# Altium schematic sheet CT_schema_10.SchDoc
size 297 x 239 mm
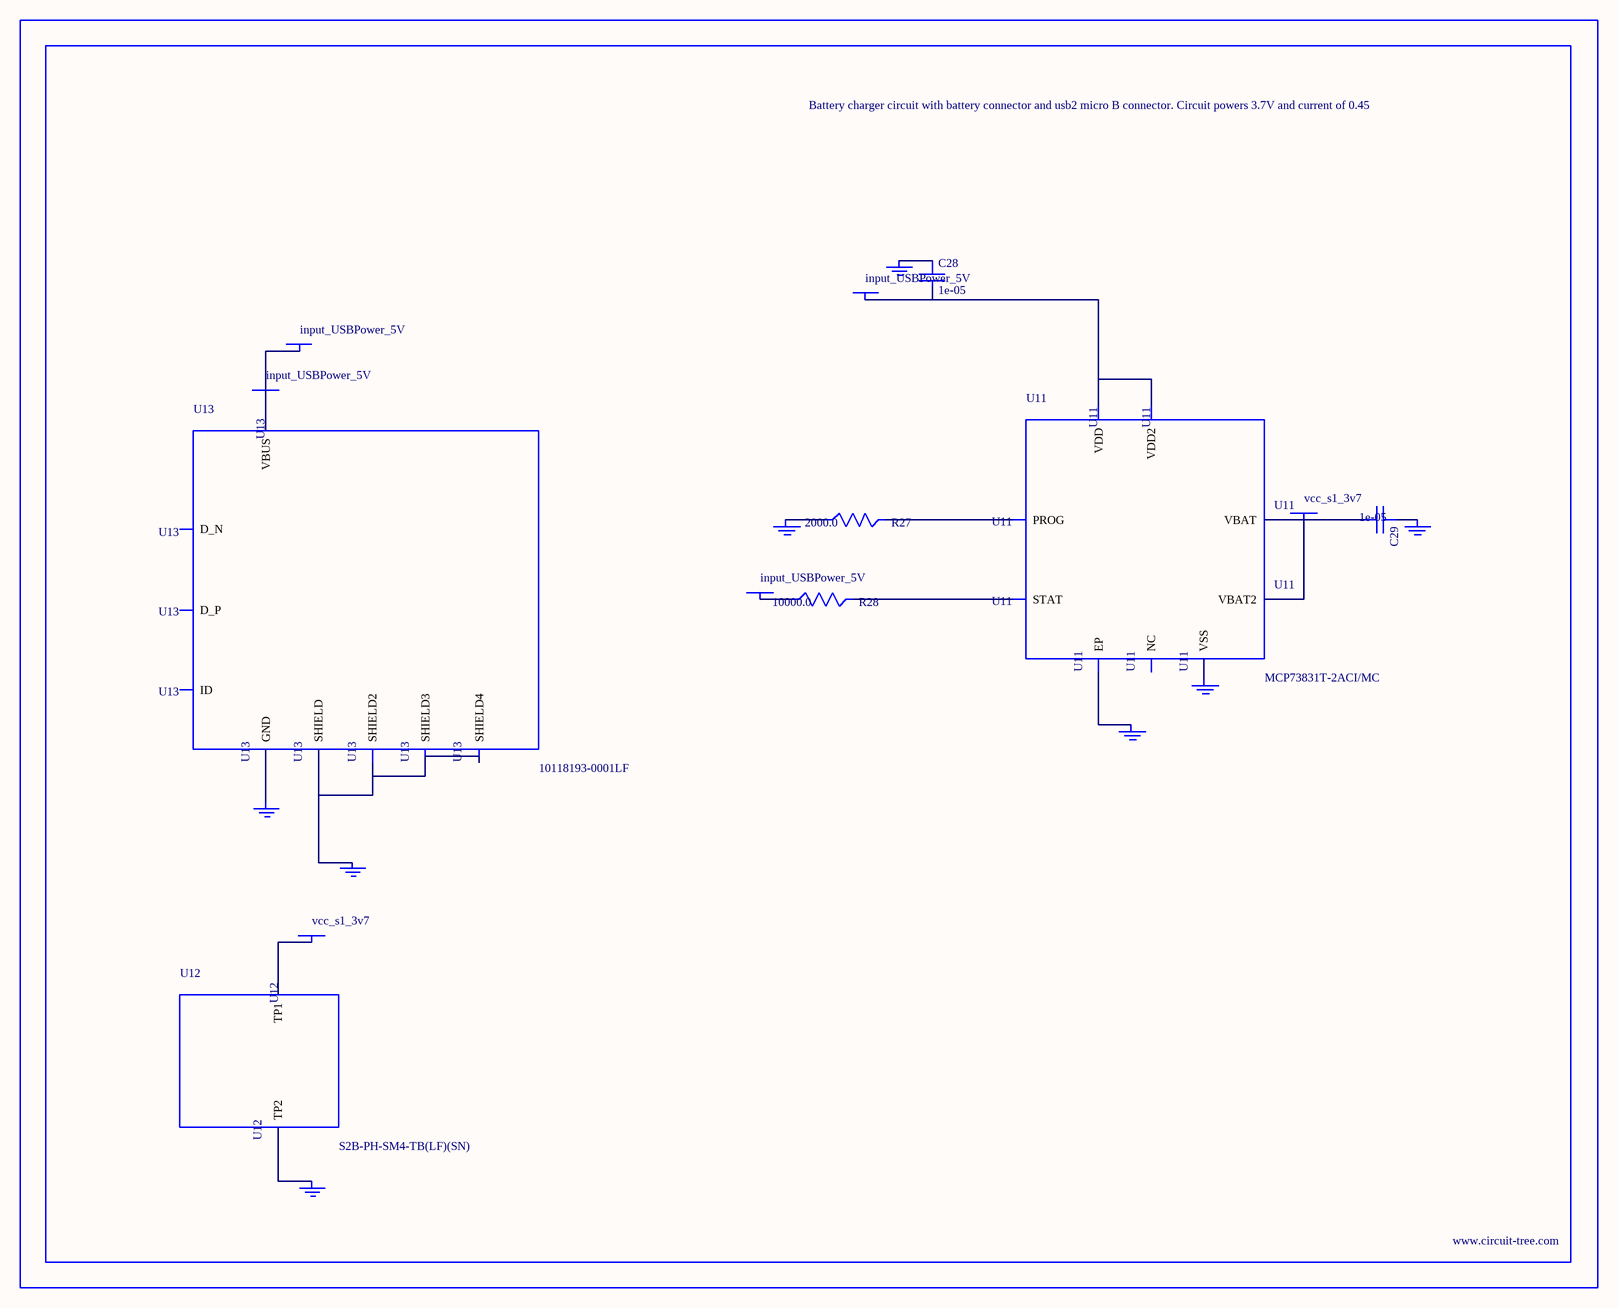
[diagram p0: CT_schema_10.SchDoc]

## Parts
BORDER9  (no value)
C28  1e-05  [C1206]
C29  1e-05  [C1206]
GND_INSTANCE_9_0  (no value)
GND_INSTANCE_9_1  (no value)
GND_INSTANCE_9_2  (no value)
GND_INSTANCE_9_3  (no value)
GND_INSTANCE_9_4  (no value)
GND_INSTANCE_9_5  (no value)
GND_INSTANCE_9_6  (no value)
GND_INSTANCE_9_7  (no value)
POWER_INSTANCE_9_0  input_USBPower_5V
POWER_INSTANCE_9_1  input_USBPower_5V
POWER_INSTANCE_9_2  vcc_s1_3v7
POWER_INSTANCE_9_3  vcc_s1_3v7
POWER_INSTANCE_9_4  input_USBPower_5V
POWER_INSTANCE_9_5  input_USBPower_5V
R27  2000.0  [R0603]
R28  10000.0  [R0603]
U11  MCP73831T-2ACI/MC  [DFN8_2X3MC]
U12  S2B-PH-SM4-TB(LF)(SN)  [JST-2-SMD]
U13  10118193-0001LF  [FCI_10118193-0001LF]

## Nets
NetC28_1: C28.1 GND_INSTANCE_9_0.0(GND)
NetC28_2: C28.2 POWER_INSTANCE_9_0.0(PWR) U11.1(VDD) U11.2(VDD2)
NetC29_1: C29.1 GND_INSTANCE_9_1.0(GND)
NetC29_2: C29.2 POWER_INSTANCE_9_2.0(PWR) U11.3(VBAT) U11.4(VBAT2)
NetGND_INSTANCE_9_2_0: GND_INSTANCE_9_2.0(GND) R27.1
NetGND_INSTANCE_9_3_0: GND_INSTANCE_9_3.0(GND) U11.9(EP)
NetGND_INSTANCE_9_4_0: GND_INSTANCE_9_4.0(GND) U11.6(VSS)
NetGND_INSTANCE_9_5_0: GND_INSTANCE_9_5.0(GND) U12.2(TP2)
NetGND_INSTANCE_9_6_0: GND_INSTANCE_9_6.0(GND) U13.6(SHIELD) U13.7(SHIELD2) U13.8(SHIELD3) U13.9(SHIELD4)
NetGND_INSTANCE_9_7_0: GND_INSTANCE_9_7.0(GND) U13.5(GND)
NetPOWER_INSTANCE_9_1_0: POWER_INSTANCE_9_1.0(PWR) R28.1
NetPOWER_INSTANCE_9_3_0: POWER_INSTANCE_9_3.0(PWR) U12.1(TP1)
NetPOWER_INSTANCE_9_4_0: POWER_INSTANCE_9_4.0(PWR) POWER_INSTANCE_9_5.0(PWR) U13.1(VBUS)
NetR27_2: R27.2 U11.8(PROG)
NetR28_2: R28.2 U11.5(STAT)

Not connected (* = marked no-connect by the designer): U11 7(NC); U13 2(D_N) 3(D_P) 4(ID)

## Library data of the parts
BORDER9 = BORDER_PAGE9
C28 C29 = C1206C106K3RACTU
GND_INSTANCE_9_0-GND_INSTANCE_9_7 = GND
POWER_INSTANCE_9_0-POWER_INSTANCE_9_5 = PWR
R27 = RC0603JR-072KL
R28 = RC0603JR-0710KL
